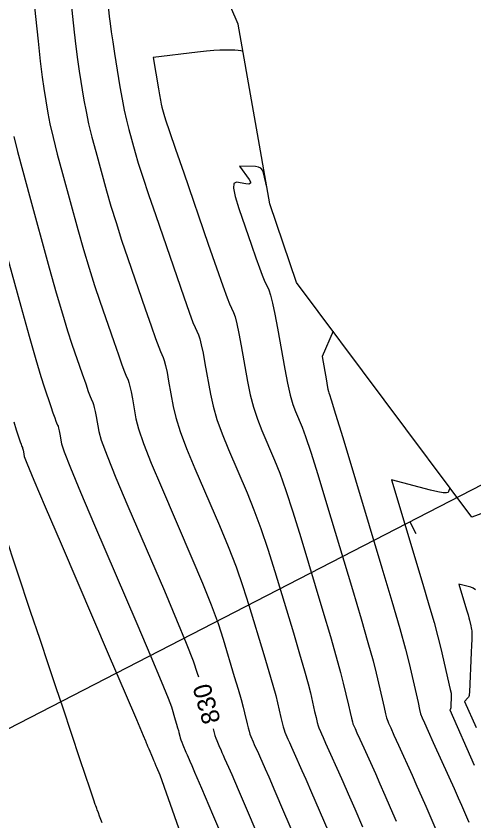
# Model space of a CAD drawing. Extents: x 1715724 to 1716561, y 394063 to 395906.
# Drawn here: x 1716070.7 to 1716106.1, y 395059.6 to 395121.9 of the extents above; entities that cross this region are included whole.
import ezdxf

# ---------------------------------------------------------------- set-up
doc = ezdxf.new("R2010")
doc.units = 0
for name, color, linetype in [('DT_X_Contour_Major', 7, 'Continuous'), ('DT_X_Contour_Minor', 7, 'Continuous'), ('DT_X_TIN_Hull', 7, 'Continuous'), ('GE_P_CL_10', 7, 'Continuous')]:
    doc.layers.add(name, color=color, linetype=linetype)

msp = doc.modelspace()

# ---------------------------------------------------------------- linework, layer by layer
at = {"layer": 'DT_X_Contour_Major'}
for points in [[(1716070.538, 395112.557), (1716070.815, 395111.404), (1716071.213, 395109.876), (1716071.731, 395107.973), (1716073.275, 395102.397), (1716073.818, 395100.459), (1716074.292, 395098.828), (1716074.695, 395097.503), (1716075.029, 395096.486), (1716075.824, 395094.18), (1716076.091, 395093.411), (1716076.295, 395092.832), (1716076.437, 395092.443), (1716076.516, 395092.244), (1716076.642, 395091.967), (1716076.693, 395091.821), (1716076.752, 395091.593), (1716076.818, 395091.283), (1716076.891, 395090.889), (1716077.097, 395089.73), (1716077.297, 395089.043), (1716077.741, 395087.85), (1716078.43, 395086.152), (1716079.363, 395083.949), (1716082.179, 395077.401), (1716083.131, 395075.162), (1716083.873, 395073.354), (1716084.405, 395071.979), (1716084.729, 395071.036), (1716084.815, 395070.747)], [(1716090.113, 395108.625), (1716089.856, 395109.737), (1716089.775, 395109.946), (1716089.643, 395110.097), (1716089.459, 395110.19), (1716089.224, 395110.225), (1716088.007, 395110.254), (1716088.739, 395109.235), (1716088.842, 395109.049), (1716088.836, 395108.929), (1716088.722, 395108.876), (1716088.5, 395108.888), (1716087.762, 395109.008), (1716087.566, 395108.914), (1716087.531, 395108.544), (1716087.656, 395107.897), (1716087.943, 395106.972), (1716088.921, 395104.138), (1716089.258, 395103.172), (1716089.536, 395102.401), (1716089.755, 395101.825), (1716089.914, 395101.443), (1716090.261, 395100.684), (1716090.401, 395100.286), (1716090.561, 395099.661), (1716090.742, 395098.81), (1716090.943, 395097.733), (1716091.507, 395094.558), (1716091.716, 395093.459), (1716091.921, 395092.544), (1716092.123, 395091.813), (1716092.321, 395091.265), (1716092.844, 395090.05), (1716093.109, 395089.339), (1716093.513, 395088.12), (1716094.055, 395086.391), (1716094.735, 395084.153), (1716096.734, 395077.506), (1716097.411, 395075.232), (1716097.944, 395073.393), (1716098.332, 395071.991), (1716098.576, 395071.025), (1716099.033, 395069.03), (1716099.186, 395068.369), (1716099.301, 395067.883), (1716099.378, 395067.573), (1716099.417, 395067.437), (1716099.472, 395067.308), (1716099.539, 395067.157), (1716099.7, 395066.798), (1716099.955, 395066.234), (1716100.303, 395065.462), (1716101.355, 395063.13), (1716101.737, 395062.28), (1716102.092, 395061.478), (1716102.421, 395060.724), (1716102.723, 395060.019), (1716103.495, 395058.204)], [(1716085.963, 395066.708), (1716085.983, 395066.624), (1716086.036, 395066.41), (1716086.098, 395066.203), (1716086.167, 395066.003), (1716086.243, 395065.811), (1716086.457, 395065.307), (1716086.542, 395065.111), (1716086.634, 395064.899), (1716086.735, 395064.671), (1716086.845, 395064.427), (1716087.148, 395063.756), (1716087.392, 395063.194), (1716087.898, 395062.014), (1716088.665, 395060.216), (1716089.693, 395057.798)]]:
    msp.add_lwpolyline(points, dxfattribs=at)
at = {"layer": 'DT_X_Contour_Minor'}
for points in [[(1716071.219, 395131.545), (1716072.204, 395121.848), (1716072.404, 395119.94), (1716072.579, 395118.373), (1716072.731, 395117.146), (1716072.859, 395116.26), (1716073.169, 395114.351), (1716073.326, 395113.522), (1716073.567, 395112.468), (1716073.89, 395111.188), (1716074.297, 395109.683), (1716075.491, 395105.367), (1716075.934, 395103.806), (1716076.364, 395102.357), (1716076.784, 395101.022), (1716077.191, 395099.801), (1716078.263, 395096.694), (1716078.623, 395095.657), (1716078.898, 395094.876), (1716079.089, 395094.352), (1716079.195, 395094.084), (1716079.366, 395093.71), (1716079.435, 395093.514), (1716079.514, 395093.207), (1716079.603, 395092.788), (1716079.702, 395092.258), (1716079.979, 395090.696), (1716080.18, 395089.926), (1716080.577, 395088.789), (1716081.168, 395087.285), (1716081.955, 395085.413), (1716084.312, 395079.931), (1716085.126, 395077.997), (1716085.801, 395076.307), (1716086.335, 395074.862), (1716086.73, 395073.659), (1716087.596, 395070.779), (1716087.89, 395069.793), (1716088.121, 395068.996), (1716088.289, 395068.389), (1716088.394, 395067.97), (1716088.593, 395067.105), (1716088.666, 395066.802), (1716088.738, 395066.539), (1716088.809, 395066.317), (1716088.878, 395066.136), (1716089.06, 395065.708), (1716089.141, 395065.52), (1716089.248, 395065.279), (1716089.379, 395064.983), (1716089.536, 395064.634), (1716089.989, 395063.63), (1716090.261, 395063.011), (1716090.737, 395061.907), (1716091.416, 395060.317), (1716092.299, 395058.242)], [(1716074.457, 395127.767), (1716075.06, 395121.838), (1716075.19, 395120.621), (1716075.322, 395119.511), (1716075.456, 395118.508), (1716075.591, 395117.613), (1716075.955, 395115.368), (1716076.115, 395114.488), (1716076.319, 395113.532), (1716076.568, 395112.5), (1716076.863, 395111.393), (1716077.708, 395108.338), (1716078.049, 395107.153), (1716078.437, 395105.887), (1716078.872, 395104.541), (1716079.354, 395103.116), (1716080.703, 395099.207), (1716081.155, 395097.903), (1716081.502, 395096.921), (1716081.741, 395096.261), (1716081.875, 395095.923), (1716082.09, 395095.453), (1716082.176, 395095.207), (1716082.276, 395094.821), (1716082.388, 395094.294), (1716082.512, 395093.627), (1716082.861, 395091.661), (1716083.064, 395090.809), (1716083.413, 395089.728), (1716083.907, 395088.417), (1716084.546, 395086.876), (1716086.445, 395082.461), (1716087.122, 395080.833), (1716087.729, 395079.261), (1716088.265, 395077.744), (1716088.731, 395076.283), (1716089.881, 395072.461), (1716090.27, 395071.153), (1716090.576, 395070.096), (1716090.8, 395069.289), (1716090.94, 395068.734), (1716091.203, 395067.586), (1716091.296, 395067.194), (1716091.379, 395066.875), (1716091.451, 395066.631), (1716091.513, 395066.461), (1716091.741, 395065.929), (1716091.861, 395065.659), (1716092.023, 395065.296), (1716092.228, 395064.841), (1716092.831, 395063.505), (1716093.13, 395062.829), (1716093.575, 395061.8), (1716094.167, 395060.419), (1716094.905, 395058.686)], [(1716077.696, 395123.989), (1716077.915, 395121.828), (1716077.976, 395121.301), (1716078.065, 395120.649), (1716078.18, 395119.87), (1716078.324, 395118.966), (1716078.742, 395116.384), (1716078.903, 395115.453), (1716079.071, 395114.596), (1716079.246, 395113.813), (1716079.429, 395113.103), (1716079.925, 395111.309), (1716080.164, 395110.5), (1716080.509, 395109.417), (1716080.96, 395108.06), (1716081.517, 395106.431), (1716083.142, 395101.721), (1716083.687, 395100.148), (1716084.105, 395098.965), (1716084.394, 395098.17), (1716084.555, 395097.763), (1716084.813, 395097.197), (1716084.918, 395096.9), (1716085.038, 395096.434), (1716085.173, 395095.799), (1716085.323, 395094.996), (1716085.743, 395092.627), (1716085.948, 395091.693), (1716086.249, 395090.667), (1716086.646, 395089.549), (1716087.138, 395088.339), (1716088.578, 395084.99), (1716089.118, 395083.668), (1716089.657, 395082.214), (1716090.195, 395080.626), (1716090.733, 395078.906), (1716092.165, 395074.142), (1716092.65, 395072.512), (1716093.032, 395071.195), (1716093.31, 395070.19), (1716093.485, 395069.497), (1716093.813, 395068.068), (1716093.926, 395067.585), (1716094.019, 395067.211), (1716094.093, 395066.945), (1716094.148, 395066.786), (1716094.266, 395066.508), (1716094.34, 395066.338), (1716094.474, 395066.038), (1716094.667, 395065.608), (1716094.92, 395065.048), (1716095.672, 395063.38), (1716095.999, 395062.646), (1716096.414, 395061.692), (1716096.918, 395060.521), (1716097.511, 395059.131)], [(1716088.313, 395118.914), (1716088.265, 395119.12), (1716088.218, 395119.159), (1716088.098, 395119.189), (1716087.905, 395119.21), (1716087.638, 395119.222), (1716086.828, 395119.241), (1716086.47, 395119.236), (1716086.005, 395119.207), (1716085.432, 395119.155), (1716084.751, 395119.078), (1716081.324, 395118.667), (1716081.716, 395116.249), (1716081.796, 395115.771), (1716081.869, 395115.372), (1716081.936, 395115.053), (1716081.994, 395114.813), (1716082.142, 395114.28), (1716082.28, 395113.846), (1716082.582, 395112.946), (1716083.048, 395111.579), (1716083.679, 395109.746), (1716085.581, 395104.234), (1716086.219, 395102.394), (1716086.708, 395101.009), (1716087.046, 395100.079), (1716087.234, 395099.603), (1716087.537, 395098.94), (1716087.659, 395098.593), (1716087.8, 395098.048), (1716087.957, 395097.305), (1716088.133, 395096.364), (1716088.625, 395093.593), (1716088.832, 395092.576), (1716089.085, 395091.606), (1716089.385, 395090.681), (1716089.73, 395089.802), (1716090.711, 395087.52), (1716091.113, 395086.504), (1716091.585, 395085.167), (1716092.125, 395083.509), (1716092.734, 395081.53), (1716094.449, 395075.824), (1716095.031, 395073.872), (1716095.488, 395072.294), (1716095.821, 395071.09), (1716096.03, 395070.261), (1716096.423, 395068.549), (1716096.556, 395067.977), (1716096.66, 395067.547), (1716096.736, 395067.259), (1716096.782, 395067.112), (1716096.869, 395066.908), (1716096.94, 395066.747), (1716097.087, 395066.418), (1716097.311, 395065.921), (1716097.611, 395065.255), (1716098.514, 395063.255), (1716098.868, 395062.463), (1716099.253, 395061.585), (1716099.67, 395060.623), (1716100.117, 395059.575)], [(1716069.165, 395106.262), (1716071.058, 395099.426), (1716071.703, 395097.112), (1716072.22, 395095.298), (1716072.607, 395093.984), (1716072.866, 395093.171), (1716073.385, 395091.667), (1716073.559, 395091.165), (1716073.692, 395090.787), (1716073.785, 395090.534), (1716073.836, 395090.404), (1716073.919, 395090.223), (1716073.952, 395090.128), (1716073.99, 395089.98), (1716074.033, 395089.777), (1716074.081, 395089.52), (1716074.215, 395088.764), (1716074.413, 395088.159), (1716074.905, 395086.911), (1716075.691, 395085.02), (1716076.772, 395082.486), (1716080.046, 395074.872), (1716081.135, 395072.326), (1716081.945, 395070.401), (1716082.476, 395069.097), (1716082.727, 395068.413), (1716083.027, 395067.415), (1716083.129, 395067.074), (1716083.209, 395066.798), (1716083.267, 395066.588), (1716083.304, 395066.443), (1716083.372, 395066.143), (1716083.406, 395066.018), (1716083.457, 395065.867), (1716083.524, 395065.689), (1716083.608, 395065.485), (1716083.854, 395064.907), (1716083.942, 395064.702), (1716084.021, 395064.519), (1716084.092, 395064.358), (1716084.153, 395064.22), (1716084.306, 395063.881), (1716084.523, 395063.377), (1716085.059, 395062.122), (1716085.913, 395060.114), (1716087.087, 395057.353)], [(1716095.236, 395097.496), (1716094.39, 395095.517), (1716094.722, 395093.643), (1716094.787, 395093.285), (1716094.841, 395093.013), (1716094.883, 395092.828), (1716094.913, 395092.728), (1716094.977, 395092.579), (1716095.105, 395092.175), (1716095.441, 395091.073), (1716095.985, 395089.273), (1716099.018, 395079.188), (1716099.791, 395076.591), (1716100.4, 395074.492), (1716100.843, 395072.891), (1716101.121, 395071.788), (1716101.816, 395068.761), (1716101.941, 395068.219), (1716102.02, 395067.887), (1716102.052, 395067.762), (1716102.075, 395067.708), (1716102.139, 395067.566), (1716102.313, 395067.178), (1716102.598, 395066.546), (1716102.994, 395065.669), (1716104.197, 395063.005), (1716104.606, 395062.097), (1716104.931, 395061.37), (1716105.172, 395060.826), (1716105.329, 395060.464), (1716105.637, 395059.74), (1716105.739, 395059.501)], [(1716070.519, 395090.465), (1716070.704, 395089.856), (1716070.946, 395089.154), (1716071.027, 395088.919), (1716071.089, 395088.743), (1716071.132, 395088.625), (1716071.156, 395088.564), (1716071.195, 395088.48), (1716071.21, 395088.435), (1716071.228, 395088.366), (1716071.248, 395088.271), (1716071.271, 395088.152), (1716071.333, 395087.799), (1716071.529, 395087.276), (1716072.069, 395085.972), (1716072.952, 395083.888), (1716074.18, 395081.023), (1716077.914, 395072.342), (1716079.139, 395069.491), (1716080.017, 395067.448), (1716080.546, 395066.215), (1716080.726, 395065.789), (1716080.743, 395065.733), (1716080.749, 395065.714), (1716080.753, 395065.699), (1716080.756, 395065.687), (1716080.758, 395065.679), (1716080.762, 395065.662), (1716080.777, 395065.626), (1716080.817, 395065.53), (1716080.882, 395065.375), (1716080.973, 395065.16), (1716081.251, 395064.507), (1716081.342, 395064.293), (1716081.408, 395064.139), (1716081.448, 395064.045), (1716081.462, 395064.012), (1716081.465, 395064.006), (1716081.473, 395063.988), (1716081.493, 395063.939), (1716081.527, 395063.86), (1716081.574, 395063.749), (1716081.823, 395063.163), (1716086.328, 395050.409)], [(1716104.292, 395085.374), (1716104.138, 395085.014), (1716104.028, 395084.968), (1716103.765, 395084.983), (1716103.349, 395085.06), (1716102.78, 395085.198), (1716099.764, 395085.986), (1716102.188, 395077.926), (1716102.664, 395076.32), (1716103.054, 395074.955), (1716103.358, 395073.83), (1716103.576, 395072.948), (1716104.304, 395069.764), (1716104.37, 395069.469), (1716104.393, 395069.361), (1716104.395, 395069.323), (1716104.395, 395069.292), (1716104.389, 395069.124), (1716104.364, 395068.579), (1716104.357, 395068.442), (1716104.348, 395068.341), (1716104.338, 395068.275), (1716104.327, 395068.243), (1716104.272, 395068.178), (1716106.157, 395063.903)], [(1716077.357, 395059.436), (1716077.166, 395059.975), (1716077.08, 395060.214), (1716076.991, 395060.451), (1716076.957, 395060.544), (1716076.92, 395060.646), (1716076.88, 395060.757), (1716076.837, 395060.877), (1716076.72, 395061.21), (1716076.62, 395061.503), (1716076.408, 395062.132), (1716076.084, 395063.098), (1716075.648, 395064.4), (1716074.335, 395068.322), (1716073.809, 395069.893), (1716073.216, 395071.665), (1716072.556, 395073.637), (1716071.829, 395075.811), (1716069.799, 395081.874)], [(1716106.274, 395077.483), (1716106.095, 395077.597), (1716105.904, 395077.669), (1716104.983, 395077.91), (1716105.501, 395076.187), (1716105.603, 395075.843), (1716105.686, 395075.551), (1716105.751, 395075.311), (1716105.798, 395075.122), (1716105.897, 395074.687), (1716105.931, 395074.536), (1716105.955, 395074.41), (1716105.971, 395074.308), (1716105.979, 395074.231), (1716105.988, 395074.058), (1716105.988, 395073.92), (1716105.979, 395073.635), (1716105.962, 395073.202), (1716105.937, 395072.623), (1716105.801, 395069.577), (1716105.782, 395069.341), (1716105.772, 395069.289), (1716105.75, 395069.234), (1716105.716, 395069.176), (1716105.67, 395069.116), (1716105.426, 395068.827), (1716106.309, 395066.823)]]:
    msp.add_lwpolyline(points, dxfattribs=at)
at = {"layer": 'DT_X_TIN_Hull'}
msp.add_lwpolyline([(1716335.246, 395223.509), (1716320.65, 395211.924), (1716306.732, 395206.826), (1716291.707, 395204.036), (1716278.005, 395208.188), (1716261.045, 395202.977), (1716243.981, 395193.78), (1716225.98, 395181.666), (1716214.77, 395165.024), (1716203.323, 395152.499), (1716198.083, 395146.196), (1716187.292, 395139.292), (1716176.967, 395127.466), (1716165.6, 395115.641), (1716155.482, 395107.53), (1716139.016, 395097.434), (1716122.723, 395086.974), (1716119.117, 395087.955), (1716105.991, 395083.1), (1716092.42, 395101.266), (1716090.336, 395107.35), (1716087.904, 395121.249), (1716081.11, 395137.012), (1716069.702, 395157.325)], dxfattribs=at)
at = {"layer": 'GE_P_CL_10'}
for p, q in [((1716111.51, 395088.045), (1715997.389, 395029.305)), ((1716101.189, 395082.733), (1716101.647, 395081.844))]:
    msp.add_line(p, q, dxfattribs=at)

# ---------------------------------------------------------------- texts
at = {"layer": 'DT_X_Contour_Major'}
msp.add_text('830', height=1.4, rotation=105.86359, dxfattribs=at).set_placement((1716086.548, 395067.326))

doc.saveas('drawing.dxf')
